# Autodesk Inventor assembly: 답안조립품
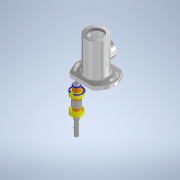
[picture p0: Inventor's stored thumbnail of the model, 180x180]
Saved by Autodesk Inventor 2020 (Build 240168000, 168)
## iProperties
Created: 2022-05
Part Number: 답안조립품
Document SubType Name: Assembly
Designer: Student
Author: Student
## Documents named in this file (10)
- C:\Users\Student\Desktop\720506V1016\답안조립품.iam
- C:\Users\Student\Desktop\720506V1016\본체.ipt
- C:\Users\Student\Desktop\720506V1016\축.ipt
- C:\Users\Student\Desktop\720506V1016\베어링 6202.ipt
- C:\Users\Student\Desktop\720506V1016\부시1.ipt
- C:\Users\Student\Desktop\720506V1016\멈춤링 15 x 1.ipt
- C:\Users\Student\Desktop\720506V1016\멈춤링 35 x 1.6.ipt
- C:\Users\Student\Desktop\720506V1016\부시2.ipt
- C:\Users\Student\Desktop\720506V1016\와셔 10 x 21.ipt
- C:\Users\Student\Desktop\720506V1016\너트 M10.ipt
